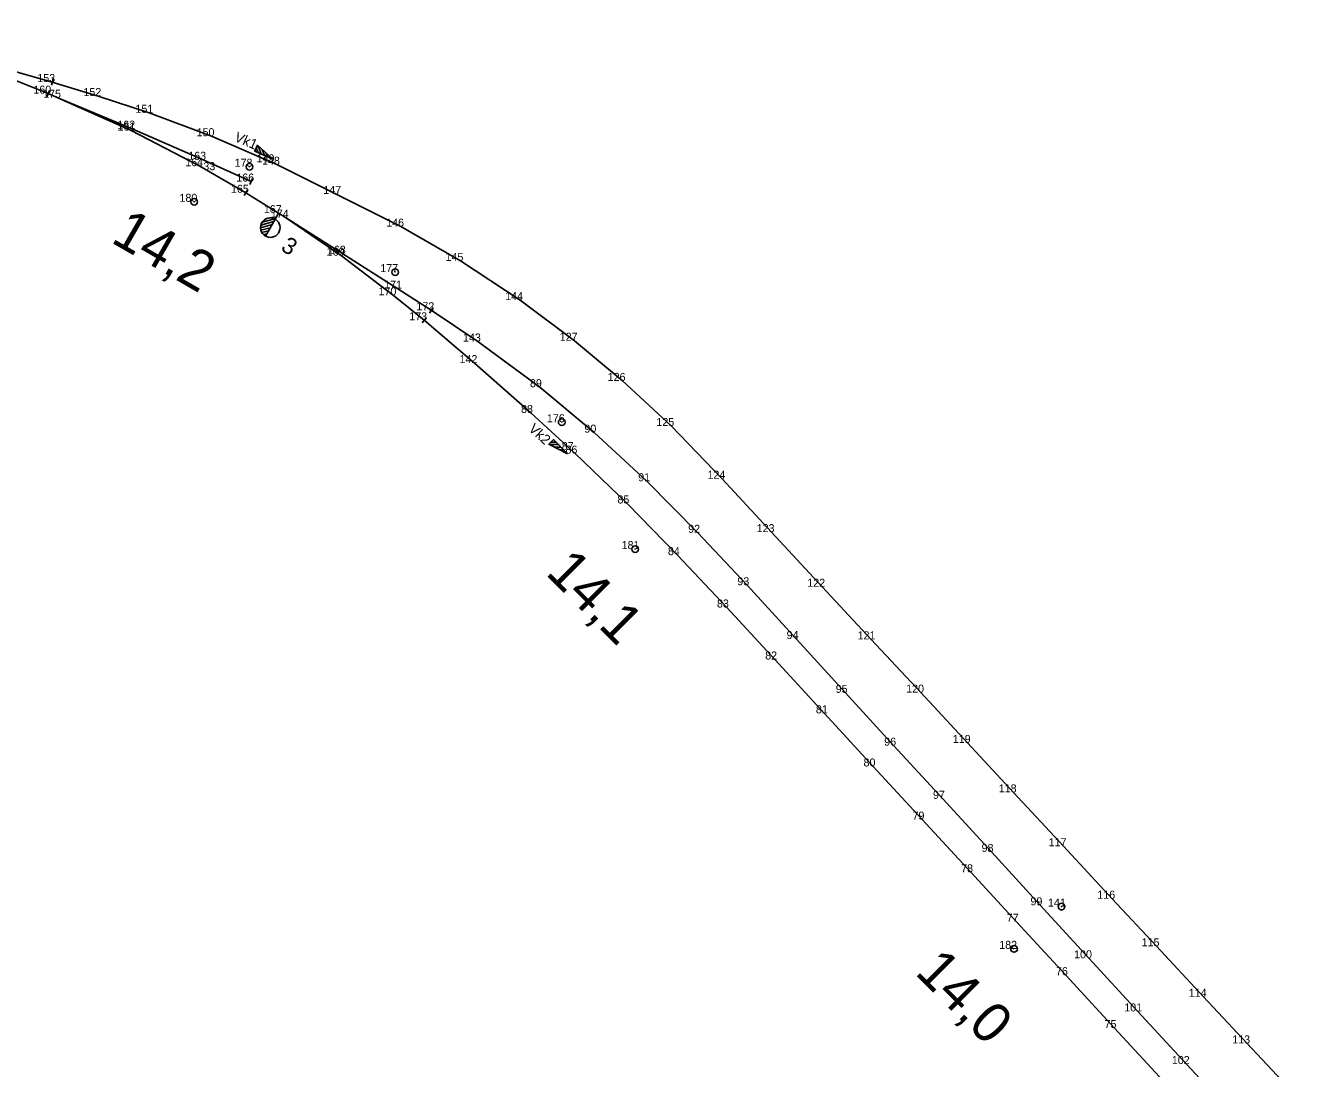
# Model space of a CAD drawing. Extents: x -554814 to -554052, y -1115925 to -1115523.
# Drawn here: x -554550.8 to -554360.9, y -1115706.4 to -1115549.9 of the extents above; entities that cross this region are included whole.
import ezdxf

# ---------------------------------------------------------------- set-up
doc = ezdxf.new("R2010")
doc.units = 0
for name, color, linetype in [('Vrstva 1', 7, 'Continuous'), ('Vrstva 2', 7, 'Continuous'), ('Vrstva 3', 7, 'Continuous'), ('Vrstva 50', 7, 'Continuous'), ('Vrstva 60', 7, 'Continuous'), ('Vrstva 7', 7, 'Continuous')]:
    doc.layers.add(name, color=color, linetype=linetype)

msp = doc.modelspace()

# ---------------------------------------------------------------- linework, layer by layer
at = {"layer": 'Vrstva 1'}
for points in [[(-554547.34, -1115560.14), (-554552.85, -1115557.9), (-554561.96, -1115554.19), (-554571.31, -1115550.37), (-554572.47, -1115549.89)], [(-554360.91, -1115709.73), (-554367.59, -1115702.57), (-554374.11, -1115695.58), (-554381.18, -1115688.01), (-554387.82, -1115680.87), (-554395.12, -1115673), (-554402.6, -1115664.92), (-554409.49, -1115657.51), (-554416.49, -1115649.97), (-554423.95, -1115641.98), (-554431.31, -1115634.09), (-554438.89, -1115625.9), (-554446.27, -1115617.89), (-554453.92, -1115609.98), (-554461.23, -1115603.22), (-554468.43, -1115597.19), (-554476.6, -1115591.1), (-554485.54, -1115585.23), (-554494.45, -1115580.08), (-554513.05, -1115570.79), (-554513.86, -1115570.43), (-554522.86, -1115566.52), (-554532.22, -1115563.01), (-554539.84, -1115560.5), (-554546.75, -1115558.4), (-554552.5, -1115556.77)], [(-554516.91, -1115573.32), (-554524.11, -1115570.06), (-554534.76, -1115565.4), (-554545.87, -1115560.75), (-554547.34, -1115560.14)], [(-554512.79, -1115578.06), (-554517.7, -1115575), (-554524.58, -1115571.02), (-554534.9, -1115565.68), (-554545.87, -1115560.75), (-554547.34, -1115560.14)], [(-554369.34, -1115713.57), (-554376.66, -1115705.67), (-554383.97, -1115697.78), (-554391.3, -1115689.81), (-554398.6, -1115681.86), (-554405.93, -1115673.86), (-554413.23, -1115665.89), (-554420.54, -1115657.92), (-554427.8, -1115650), (-554435.17, -1115641.93), (-554442.56, -1115633.87), (-554449.93, -1115626), (-554457.61, -1115618.27), (-554465.49, -1115610.98), (-554473.64, -1115604.16), (-554482.93, -1115597.31), (-554489.91, -1115592.62), (-554494.94, -1115589.39), (-554503.18, -1115584.15), (-554511.74, -1115578.72), (-554512.79, -1115578.06)], [(-554380.14, -1115708.23), (-554387.49, -1115700.26), (-554394.79, -1115692.34), (-554402.17, -1115684.33), (-554409.01, -1115676.91), (-554416.3, -1115669.01), (-554423.64, -1115661.04), (-554430.96, -1115653.08), (-554438.39, -1115645), (-554445.6, -1115637.2), (-554452.97, -1115629.35), (-554460.53, -1115621.6), (-554468.33, -1115614.12), (-554468.89, -1115613.59), (-554474.98, -1115608.03), (-554483.45, -1115600.55), (-554490.98, -1115594.13), (-554495.59, -1115590.39), (-554503.36, -1115584.44), (-554511.74, -1115578.72), (-554512.79, -1115578.06)]]:
    msp.add_lwpolyline(points, dxfattribs=at)
at = {"layer": 'Vrstva 2'}
for p, q in [((-554546.84, -1115558.89), (-554546.57, -1115557.93)), ((-554547.52, -1115560.61), (-554547.15, -1115559.68)), ((-554517.12, -1115573.78), (-554516.71, -1115572.87)), ((-554517.96, -1115575.43), (-554517.45, -1115574.56)), ((-554513.3, -1115578.95), (-554512.79, -1115578.06)), ((-554513.78, -1115579.78), (-554515.49, -1115580.24)), ((-554513.51, -1115579.32), (-554515.44, -1115579.84)), ((-554514.04, -1115580.24), (-554515.44, -1115580.62)), ((-554513.4, -1115578.91), (-554515.23, -1115579.4)), ((-554513.3, -1115578.96), (-554514.76, -1115581.49)), ((-554513.3, -1115578.96), (-554513.3, -1115578.96)), ((-554514.31, -1115580.7), (-554515.29, -1115580.96)), ((-554514.57, -1115581.16), (-554515.03, -1115581.28)), ((-554491.29, -1115594.52), (-554490.66, -1115593.74)), ((-554490.18, -1115593.04), (-554489.63, -1115592.21))]:
    msp.add_line(p, q, dxfattribs=at)
msp.add_circle((-554514.04, -1115580.23), 1.46, dxfattribs=at)
msp.add_arc((-554514.03, -1115580.22), 1.46, 60.0196, 239.9804, dxfattribs=at)
at = {"layer": 'Vrstva 3'}
for p, q in [((-554516.35, -1115568.79), (-554516.35, -1115568.77)), ((-554515.88, -1115569), (-554516.14, -1115568.29)), ((-554515.4, -1115569.21), (-554515.88, -1115567.96)), ((-554514.92, -1115569.42), (-554515.26, -1115568.51)), ((-554514.44, -1115569.63), (-554514.66, -1115569.06)), ((-554513.95, -1115569.84), (-554514.05, -1115569.62)), ((-554471.18, -1115612.4), (-554471.95, -1115612.39)), ((-554471.56, -1115612.02), (-554471.57, -1115612.02)), ((-554470.81, -1115612.78), (-554472.18, -1115612.77)), ((-554470.44, -1115613.16), (-554471.43, -1115613.15)), ((-554470.07, -1115613.53), (-554470.68, -1115613.53)), ((-554469.7, -1115613.91), (-554469.94, -1115613.91))]:
    msp.add_line(p, q, dxfattribs=at)
for points in [[(-554513.66, -1115569.97), (-554515.96, -1115567.88), (-554516.36, -1115568.79), (-554513.66, -1115569.97)], [(-554469.46, -1115614.15), (-554472.28, -1115612.71), (-554471.56, -1115612.01), (-554469.46, -1115614.15)]]:
    msp.add_lwpolyline(points, dxfattribs=at)
at = {"layer": 'Vrstva 50'}
for p, q in [((-554517.11, -1115571.12), (-554517.2, -1115571.08)), ((-554495.28, -1115586.93), (-554495.37, -1115586.88)), ((-554470.32, -1115609.45), (-554470.39, -1115609.39))]:
    msp.add_line(p, q, dxfattribs=at)
for centre in [(-554517.16, -1115571.1), (-554495.33, -1115586.9), (-554470.35, -1115609.42)]:
    msp.add_circle(centre, 0.5, dxfattribs=at)
at = {"layer": 'Vrstva 60'}
for p, q in [((-554546.75, -1115558.4), (-554546.75, -1115558.4)), ((-554547.34, -1115560.14), (-554547.34, -1115560.14)), ((-554545.87, -1115560.75), (-554545.87, -1115560.75)), ((-554539.84, -1115560.5), (-554539.84, -1115560.5)), ((-554532.22, -1115563.01), (-554532.22, -1115563.01)), ((-554534.9, -1115565.68), (-554534.9, -1115565.68)), ((-554534.76, -1115565.4), (-554534.76, -1115565.4)), ((-554522.86, -1115566.52), (-554522.86, -1115566.52)), ((-554524.11, -1115570.06), (-554524.11, -1115570.06)), ((-554513.86, -1115570.43), (-554513.86, -1115570.43)), ((-554513.05, -1115570.79), (-554513.05, -1115570.79)), ((-554524.58, -1115571.02), (-554524.58, -1115571.02)), ((-554517.16, -1115571.1), (-554517.16, -1115571.1)), ((-554516.91, -1115573.32), (-554516.91, -1115573.32)), ((-554525.44, -1115576.36), (-554525.44, -1115576.36)), ((-554517.7, -1115575), (-554517.7, -1115575)), ((-554503.86, -1115575.18), (-554503.86, -1115575.18)), ((-554512.79, -1115578.06), (-554512.79, -1115578.06)), ((-554511.74, -1115578.72), (-554511.74, -1115578.72)), ((-554494.45, -1115580.08), (-554494.45, -1115580.08)), ((-554503.18, -1115584.15), (-554503.18, -1115584.15)), ((-554503.36, -1115584.44), (-554503.36, -1115584.44)), ((-554485.54, -1115585.23), (-554485.54, -1115585.23)), ((-554495.33, -1115586.9), (-554495.33, -1115586.9)), ((-554494.94, -1115589.39), (-554494.94, -1115589.39)), ((-554495.59, -1115590.39), (-554495.59, -1115590.39)), ((-554476.6, -1115591.1), (-554476.6, -1115591.1)), ((-554489.91, -1115592.62), (-554489.91, -1115592.62)), ((-554490.97, -1115594.13), (-554490.97, -1115594.13)), ((-554482.93, -1115597.31), (-554482.93, -1115597.31)), ((-554468.43, -1115597.19), (-554468.43, -1115597.19)), ((-554483.45, -1115600.55), (-554483.45, -1115600.55)), ((-554461.23, -1115603.22), (-554461.23, -1115603.22)), ((-554473.64, -1115604.16), (-554473.64, -1115604.16)), ((-554474.98, -1115608.03), (-554474.98, -1115608.03)), ((-554470.35, -1115609.42), (-554470.35, -1115609.42)), ((-554453.92, -1115609.98), (-554453.92, -1115609.98)), ((-554465.49, -1115610.98), (-554465.49, -1115610.98)), ((-554468.89, -1115613.59), (-554468.89, -1115613.59)), ((-554468.33, -1115614.12), (-554468.33, -1115614.12)), ((-554457.61, -1115618.27), (-554457.61, -1115618.27)), ((-554446.27, -1115617.89), (-554446.27, -1115617.89)), ((-554460.53, -1115621.6), (-554460.53, -1115621.6)), ((-554449.93, -1115626), (-554449.93, -1115626)), ((-554438.89, -1115625.9), (-554438.89, -1115625.9)), ((-554459.33, -1115628.44), (-554459.33, -1115628.44)), ((-554452.97, -1115629.35), (-554452.97, -1115629.35)), ((-554442.56, -1115633.87), (-554442.56, -1115633.87)), ((-554431.31, -1115634.09), (-554431.31, -1115634.09)), ((-554445.6, -1115637.2), (-554445.6, -1115637.2)), ((-554435.17, -1115641.93), (-554435.17, -1115641.93)), ((-554423.95, -1115641.98), (-554423.95, -1115641.98)), ((-554438.39, -1115645), (-554438.39, -1115645)), ((-554427.8, -1115650), (-554427.8, -1115650)), ((-554416.49, -1115649.97), (-554416.49, -1115649.97)), ((-554430.96, -1115653.08), (-554430.96, -1115653.08)), ((-554420.54, -1115657.92), (-554420.54, -1115657.92)), ((-554409.49, -1115657.51), (-554409.49, -1115657.51)), ((-554423.64, -1115661.04), (-554423.64, -1115661.04)), ((-554413.23, -1115665.89), (-554413.23, -1115665.89)), ((-554402.6, -1115664.92), (-554402.6, -1115664.92)), ((-554416.3, -1115669.01), (-554416.3, -1115669.01)), ((-554395.12, -1115673), (-554395.12, -1115673)), ((-554405.93, -1115673.86), (-554405.93, -1115673.86)), ((-554409.01, -1115676.91), (-554409.01, -1115676.91)), ((-554387.82, -1115680.87), (-554387.82, -1115680.87)), ((-554398.6, -1115681.86), (-554398.6, -1115681.86)), ((-554395.42, -1115682.06), (-554395.42, -1115682.06)), ((-554402.17, -1115684.33), (-554402.17, -1115684.33)), ((-554402.54, -1115688.39), (-554402.54, -1115688.39)), ((-554381.18, -1115688.01), (-554381.18, -1115688.01)), ((-554391.3, -1115689.81), (-554391.3, -1115689.81)), ((-554394.79, -1115692.34), (-554394.79, -1115692.34)), ((-554374.11, -1115695.58), (-554374.11, -1115695.58)), ((-554383.97, -1115697.78), (-554383.97, -1115697.78)), ((-554387.49, -1115700.26), (-554387.49, -1115700.26)), ((-554367.59, -1115702.57), (-554367.59, -1115702.57)), ((-554376.66, -1115705.67), (-554376.66, -1115705.67))]:
    msp.add_line(p, q, dxfattribs=at)
at = {"layer": 'Vrstva 7'}
for p, q in [((-554525.39, -1115576.39), (-554525.48, -1115576.34)), ((-554459.3, -1115628.48), (-554459.36, -1115628.4)), ((-554395.38, -1115682.1), (-554395.45, -1115682.02)), ((-554402.51, -1115688.43), (-554402.57, -1115688.35))]:
    msp.add_line(p, q, dxfattribs=at)
for centre in [(-554525.44, -1115576.36), (-554459.33, -1115628.44), (-554395.42, -1115682.06), (-554402.54, -1115688.39)]:
    msp.add_circle(centre, 0.5, dxfattribs=at)

# ---------------------------------------------------------------- texts
at = {"layer": 'Vrstva 2'}
msp.add_text('3', height=2.5, rotation=328.046, dxfattribs=at).set_placement((-554512.6, -1115583.54))
at = {"layer": 'Vrstva 3'}
for s, rotation, p in [('Vk1', 336.5438, (-554519.54, -1115567.19)), ('Vk2', 317.5936, (-554475.42, -1115610.57))]:
    msp.add_text(s, height=1.5, rotation=rotation, dxfattribs=at).set_placement(p)
at = {"layer": 'Vrstva 60'}
for s, p in [('153', (-554548.97, -1115558.4)), ('160', (-554549.56, -1115560.14)), ('175', (-554548.1, -1115560.75)), ('152', (-554542.06, -1115560.5)), ('151', (-554534.26, -1115563.01)), ('162', (-554536.98, -1115565.4)), ('161', (-554536.94, -1115565.68)), ('150', (-554525.09, -1115566.52)), ('163', (-554526.34, -1115570.06)), ('164', (-554526.8, -1115571.02)), ('33', (-554524.08, -1115571.62)), ('178', (-554519.39, -1115571.1)), ('149', (-554516.09, -1115570.43)), ('148', (-554515.28, -1115570.79)), ('166', (-554519.14, -1115573.32)), ('165', (-554519.94, -1115575)), ('147', (-554506.09, -1115575.18)), ('180', (-554527.66, -1115576.36)), ('167', (-554515.01, -1115578.06)), ('174', (-554513.96, -1115578.72)), ('146', (-554496.67, -1115580.08)), ('169', (-554505.59, -1115584.44)), ('168', (-554505.41, -1115584.15)), ('145', (-554487.77, -1115585.23)), ('177', (-554497.55, -1115586.9)), ('170', (-554497.82, -1115590.39)), ('171', (-554496.97, -1115589.39)), ('144', (-554478.83, -1115591.1)), ('172', (-554492.13, -1115592.62)), ('173', (-554493.2, -1115594.13)), ('143', (-554485.15, -1115597.31)), ('127', (-554470.65, -1115597.19)), ('142', (-554485.67, -1115600.55)), ('89', (-554475.11, -1115604.16)), ('126', (-554463.46, -1115603.22)), ('88', (-554476.45, -1115608.03)), ('176', (-554472.58, -1115609.42)), ('125', (-554456.16, -1115609.98)), ('90', (-554466.95, -1115610.98)), ('87', (-554470.35, -1115613.59)), ('86', (-554469.79, -1115614.12)), ('91', (-554458.88, -1115618.27)), ('124', (-554448.49, -1115617.89)), ('85', (-554462, -1115621.6)), ('92', (-554451.39, -1115626)), ('123', (-554441.12, -1115625.9)), ('181', (-554461.37, -1115628.44)), ('84', (-554454.43, -1115629.35)), ('93', (-554444.02, -1115633.87)), ('122', (-554433.53, -1115634.09)), ('83', (-554447.07, -1115637.2)), ('94', (-554436.63, -1115641.93)), ('121', (-554425.99, -1115641.98)), ('82', (-554439.84, -1115645)), ('95', (-554429.27, -1115650)), ('120', (-554418.71, -1115649.97)), ('81', (-554432.24, -1115653.08)), ('119', (-554411.72, -1115657.51)), ('96', (-554422, -1115657.92)), ('80', (-554425.1, -1115661.04)), ('118', (-554404.83, -1115664.92)), ('97', (-554414.69, -1115665.89)), ('79', (-554417.76, -1115669.01)), ('98', (-554407.4, -1115673.86)), ('117', (-554397.35, -1115673)), ('78', (-554410.47, -1115676.91)), ('99', (-554400.07, -1115681.86)), ('141', (-554397.45, -1115682.06)), ('116', (-554390.05, -1115680.87)), ('77', (-554403.63, -1115684.33)), ('182', (-554404.76, -1115688.39)), ('100', (-554393.53, -1115689.81)), ('115', (-554383.41, -1115688.01)), ('76', (-554396.25, -1115692.34)), ('114', (-554376.34, -1115695.58)), ('101', (-554386.01, -1115697.78)), ('75', (-554388.97, -1115700.26)), ('113', (-554369.82, -1115702.57)), ('102', (-554378.88, -1115705.67))]:
    msp.add_text(s, height=1.2, dxfattribs=at).set_placement(p)
at = {"layer": 'Vrstva 7'}
for s, rotation, p in [('14,2', 330, (-554538.12, -1115582.33)), ('14,1', 315, (-554472.91, -1115632.14)), ('14,0', 315, (-554417.52, -1115692.08))]:
    msp.add_text(s, height=6, rotation=rotation, dxfattribs=at).set_placement(p)

doc.saveas('drawing.dxf')
